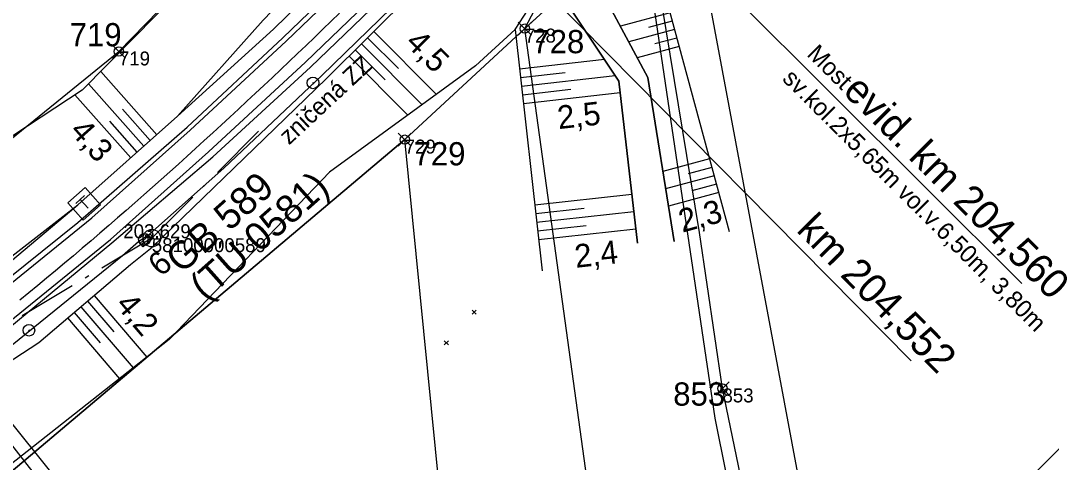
# Model space of a CAD drawing. Extents: x -800194 to -799078, y -1007177 to -1006597.
# Drawn here: x -799466.4 to -799377.8, y -1006944.2 to -1006906.1 of the extents above; entities that cross this region are included whole.
import ezdxf

# ---------------------------------------------------------------- set-up
doc = ezdxf.new("R2010")
doc.units = 0
for name, color, linetype in [('02_Osa_koleje', 7, 'Continuous'), ('Dočasné zábory', 7, 'Continuous'), ('Obvod stavby', 7, 'Continuous'), ('Vrstva 11', 7, 'Continuous'), ('Vrstva 12', 7, 'Continuous'), ('Vrstva 18', 7, 'Continuous'), ('Vrstva 3', 7, 'Continuous'), ('Vrstva 33', 7, 'Continuous'), ('Vrstva 4', 7, 'Continuous'), ('Vrstva 48', 7, 'Continuous'), ('Vrstva 49', 7, 'Continuous'), ('Vrstva 5', 7, 'Continuous'), ('Vrstva 50', 7, 'Continuous'), ('Vrstva 53', 7, 'Continuous'), ('Vrstva 55', 7, 'Continuous'), ('Vrstva 56', 7, 'Continuous'), ('Vrstva 60', 7, 'Continuous'), ('Vrstva 61', 7, 'Continuous'), ('Vrstva 63', 7, 'Continuous'), ('Vrstva 7', 7, 'Continuous')]:
    doc.layers.add(name, color=color, linetype=linetype)

msp = doc.modelspace()

# ---------------------------------------------------------------- linework, layer by layer
at = {"layer": '02_Osa_koleje'}
msp.add_lwpolyline([(-799439.012, -1006905.497), (-799439.73, -1006906.193), (-799440.449, -1006906.887), (-799441.17, -1006907.581), (-799441.891, -1006908.273), (-799442.614, -1006908.965), (-799443.338, -1006909.655), (-799444.063, -1006910.343), (-799444.789, -1006911.03), (-799445.517, -1006911.716), (-799446.246, -1006912.401), (-799446.976, -1006913.084), (-799447.708, -1006913.766), (-799448.441, -1006914.446), (-799449.175, -1006915.124), (-799449.911, -1006915.802), (-799450.649, -1006916.477), (-799451.388, -1006917.151), (-799452.128, -1006917.823), (-799452.87, -1006918.493), (-799453.614, -1006919.162), (-799454.359, -1006919.828), (-799455.106, -1006920.493), (-799455.855, -1006921.156), (-799456.605, -1006921.818), (-799457.357, -1006922.477), (-799458.111, -1006923.134), (-799458.866, -1006923.789), (-799459.623, -1006924.442), (-799460.382, -1006925.093), (-799461.143, -1006925.742), (-799461.906, -1006926.389), (-799462.671, -1006927.033), (-799463.437, -1006927.675), (-799464.206, -1006928.315), (-799464.976, -1006928.953), (-799465.749, -1006929.588), (-799466.523, -1006930.22)], dxfattribs=at)
at = {"layer": 'Dočasné zábory'}
for p, q in [((-799406.631, -1006938.384), (-799405.5, -1006937.253)), ((-799406.631, -1006937.253), (-799405.5, -1006938.384))]:
    msp.add_line(p, q, dxfattribs=at)
for points in [[(-799409.787, -1006894.075), (-799409.48, -1006895.36), (-799407.32, -1006903.81), (-799399.52, -1006945.6), (-799393.3, -1006959.22), (-799387.62, -1006968.78), (-799386.5, -1006977.04), (-799373.965, -1006992.548), (-799373.809, -1006993.118), (-799373.66, -1006993.663), (-799374.581, -1006994.49), (-799377.093, -1006995.576), (-799395.454, -1007003.287), (-799408.652, -1007008.83)], [(-799551.8, -1007065.451), (-799550.158, -1007064.738), (-799440.86, -1007028.935), (-799429.23, -1007018.29), (-799423.8, -1007012.71), (-799421.502, -1007009.702), (-799412.394, -1007002.777), (-799410.562, -1007001.808), (-799396.882, -1006994.578), (-799395.924, -1006994.071), (-799394.941, -1006993.029), (-799394.947, -1006991.657), (-799395.98, -1006986.652), (-799406.066, -1006937.818), (-799408.053, -1006924.38), (-799411.989, -1006900.28), (-799413.453, -1006897.919)]]:
    msp.add_lwpolyline(points, dxfattribs=at)
msp.add_circle((-799406.066, -1006937.818), 0.4, dxfattribs=at)
at = {"layer": 'Obvod stavby'}
for p, q in [((-799423.636, -1006907.396), (-799422.504, -1006906.264)), ((-799423.636, -1006906.264), (-799422.504, -1006907.396)), ((-799458.556, -1006909.366), (-799457.424, -1006908.234)), ((-799458.556, -1006908.234), (-799457.424, -1006909.366)), ((-799433.966, -1006916.956), (-799432.834, -1006915.824)), ((-799433.966, -1006915.824), (-799432.834, -1006916.956))]:
    msp.add_line(p, q, dxfattribs=at)
msp.add_lwpolyline([(-799559.64, -1006968.48), (-799519.68, -1006952.01), (-799500.87, -1006940.41), (-799496.64, -1006937.8), (-799494.85, -1006936.7), (-799484.52, -1006930.32), (-799457.99, -1006908.8), (-799435, -1006885.17), (-799430.26, -1006880.27), (-799425.53, -1006875.38), (-799422.55, -1006864.36), (-799416.748, -1006858.798), (-799395.763, -1006879.374), (-799413.75, -1006898.23), (-799418.41, -1006902.53), (-799423.07, -1006906.83), (-799433.4, -1006916.39), (-799469.5, -1006946.86), (-799487.22, -1006958.47), (-799495.25, -1006963.74), (-799521.98, -1006977.8), (-799546.71, -1006987.83)], dxfattribs=at)
for centre in [(-799423.07, -1006906.83), (-799457.99, -1006908.8), (-799433.4, -1006916.39)]:
    msp.add_circle(centre, 0.4, dxfattribs=at)
at = {"layer": 'Vrstva 11'}
for p, q in [((-799455.418, -1006924.635), (-799456.17, -1006925.303)), ((-799455.51, -1006925.383), (-799455.47, -1006924.681)), ((-799455.891, -1006925.459), (-799455.866, -1006925.033))]:
    msp.add_line(p, q, dxfattribs=at)
msp.add_circle((-799455.794, -1006924.969), 0.503, dxfattribs=at)
msp.add_arc((-799455.794, -1006924.969), 0.503, 221.618, 41.618, dxfattribs=at)
at = {"layer": 'Vrstva 12'}
msp.add_lwpolyline([(-799455.328, -1006924.513), (-799455.013, -1006924.859), (-799455.894, -1006925.627), (-799456.318, -1006925.174), (-799455.328, -1006924.513)], dxfattribs=at)
at = {"layer": 'Vrstva 18'}
msp.add_line((-799380.318, -1006928.766), (-799419.546, -1006889.62), dxfattribs=at)
at = {"layer": 'Vrstva 3'}
msp.add_line((-799442.19, -1006974.528), (-799473.063, -1006935.201), dxfattribs=at)
msp.add_lwpolyline([(-799439.356, -1006972.379), (-799450.062, -1006959.03), (-799451.608, -1006960.27), (-799472.235, -1006934.552)], dxfattribs=at)
at = {"layer": 'Vrstva 33'}
for p, q in [((-799461.686, -1006921.876), (-799460.938, -1006921.212)), ((-799461.312, -1006921.544), (-799460.648, -1006922.292))]:
    msp.add_line(p, q, dxfattribs=at)
msp.add_lwpolyline([(-799462.392, -1006921.835), (-799460.897, -1006920.506), (-799459.568, -1006922.001), (-799461.063, -1006923.33), (-799462.392, -1006921.835)], dxfattribs=at)
at = {"layer": 'Vrstva 4'}
for points in [[(-799510.394, -1006958.536), (-799498.027, -1006951.328), (-799477.988, -1006937.435), (-799460.33, -1006923.117), (-799451.862, -1006915.581), (-799443.604, -1006907.9), (-799435.444, -1006900.067), (-799428.64, -1006893.299), (-799422.817, -1006887.511), (-799415.998, -1006880.595), (-799408.158, -1006872.652), (-799401.02, -1006864.85)], [(-799509.248, -1006960.724), (-799497.456, -1006953.809), (-799476.495, -1006939.437), (-799458.707, -1006924.982), (-799450.277, -1006917.43), (-799441.932, -1006909.717), (-799433.783, -1006901.867), (-799426.9, -1006895.092), (-799421.037, -1006889.182), (-799414.218, -1006882.281), (-799406.443, -1006874.417), (-799398.609, -1006866.93)], [(-799511.236, -1006957.129), (-799499.236, -1006950.771), (-799498.598, -1006949.914), (-799498.679, -1006949.705), (-799496.151, -1006948.479), (-799496.251, -1006948.258), (-799490.687, -1006944.683), (-799490.497, -1006944.878), (-799488.249, -1006943.052), (-799488.105, -1006943.216), (-799486.269, -1006941.68), (-799478.997, -1006936.484), (-799474.568, -1006932.916), (-799474.237, -1006932.694), (-799461.519, -1006921.99), (-799452.935, -1006914.372), (-799444.695, -1006906.886), (-799436.579, -1006898.932), (-799429.629, -1006892.192), (-799429.07, -1006892.727), (-799423.479, -1006886.901), (-799416.56, -1006880.007), (-799417.085, -1006879.46), (-799415.349, -1006878.386)], [(-799510.726, -1006958.045), (-799497.901, -1006950.516), (-799478.36, -1006937.055), (-799461.534, -1006923.53), (-799452.128, -1006915.305), (-799443.894, -1006907.632), (-799435.739, -1006899.754), (-799428.922, -1006893.007), (-799423.223, -1006887.256), (-799416.277, -1006880.269), (-799414.896, -1006878.87)], [(-799509.087, -1006961.127), (-799497.277, -1006954.118), (-799476.183, -1006939.802), (-799458.586, -1006925.284), (-799449.914, -1006917.869), (-799441.499, -1006910.139), (-799433.371, -1006902.28), (-799426.451, -1006895.478), (-799420.657, -1006889.585), (-799413.85, -1006882.742), (-799412.388, -1006881.287)], [(-799475.489, -1006940.774), (-799457.684, -1006926.366), (-799456.318, -1006925.174), (-799455.328, -1006924.513), (-799448.961, -1006918.843), (-799440.534, -1006910.864), (-799432.566, -1006903.097), (-799428.918, -1006899.95), (-799428.131, -1006899.117), (-799425.824, -1006895.981), (-799426.173, -1006895.627), (-799420.283, -1006889.914), (-799413.647, -1006882.957), (-799413.271, -1006883.261), (-799411.693, -1006881.939)]]:
    msp.add_lwpolyline(points, dxfattribs=at)
at = {"layer": 'Vrstva 48'}
for p, q in [((-799410.574, -1006905.468), (-799414.85, -1006906.623)), ((-799410.183, -1006906.916), (-799414.124, -1006907.981)), ((-799410.379, -1006906.192), (-799412.433, -1006906.747)), ((-799436.601, -1006907.611), (-799433.948, -1006910.272)), ((-799436.07, -1006907.081), (-799430.681, -1006912.486)), ((-799409.987, -1006907.64), (-799411.874, -1006908.15)), ((-799437.663, -1006908.67), (-799435.092, -1006911.248)), ((-799437.132, -1006908.141), (-799431.908, -1006913.38)), ((-799409.792, -1006908.364), (-799413.398, -1006909.338)), ((-799438.194, -1006909.2), (-799433.135, -1006914.274)), ((-799423.526, -1006910.286), (-799416.226, -1006909.471)), ((-799454.726, -1006915.962), (-799459.558, -1006910.517)), ((-799423.443, -1006911.031), (-799419.601, -1006910.602)), ((-799423.36, -1006911.777), (-799415.291, -1006910.876)), ((-799455.848, -1006916.957), (-799460.612, -1006911.589)), ((-799423.277, -1006912.522), (-799419.11, -1006912.057)), ((-799456.97, -1006917.953), (-799461.771, -1006912.543)), ((-799423.193, -1006913.268), (-799414.858, -1006912.337)), ((-799455.287, -1006916.459), (-799457.686, -1006913.756)), ((-799456.409, -1006917.455), (-799458.774, -1006914.79)), ((-799407.172, -1006918.053), (-799411.191, -1006919.139)), ((-799406.976, -1006918.777), (-799409.024, -1006919.33)), ((-799406.781, -1006919.501), (-799410.952, -1006920.628)), ((-799406.585, -1006920.225), (-799408.709, -1006920.799)), ((-799422.218, -1006922.007), (-799413.866, -1006921.075)), ((-799406.389, -1006920.949), (-799410.713, -1006922.118)), ((-799422.135, -1006922.753), (-799417.958, -1006922.286)), ((-799422.051, -1006923.498), (-799413.697, -1006922.565)), ((-799421.968, -1006924.243), (-799417.79, -1006923.777)), ((-799421.885, -1006924.989), (-799413.528, -1006924.056)), ((-799460.115, -1006929.802), (-799455.59, -1006935.113)), ((-799461.257, -1006930.774), (-799456.769, -1006936.043)), ((-799460.686, -1006930.288), (-799458.433, -1006932.933)), ((-799462.399, -1006931.747), (-799457.948, -1006936.972)), ((-799461.828, -1006931.261), (-799459.593, -1006933.884))]:
    msp.add_line(p, q, dxfattribs=at)
at = {"layer": 'Vrstva 49'}
for p, q in [((-799423.903, -1006906.911), (-799421.584, -1006927.684)), ((-799427.607, -1006931.077), (-799427.253, -1006931.431)), ((-799427.607, -1006931.431), (-799427.253, -1006931.077)), ((-799429.993, -1006933.713), (-799429.639, -1006934.067)), ((-799429.993, -1006934.067), (-799429.639, -1006933.713))]:
    msp.add_line(p, q, dxfattribs=at)
for points in [[(-799410.227, -1006925.149), (-799412.491, -1006911.033), (-799419.106, -1006898.668), (-799423.582, -1006889.778), (-799429.735, -1006878.378), (-799431.818, -1006855.328)], [(-799426.038, -1006858.234), (-799426.419, -1006863.568), (-799427.212, -1006869.673), (-799426.968, -1006870.003), (-799426.4, -1006870.552), (-799426.115, -1006870.824), (-799426.018, -1006877.519), (-799424.103, -1006883.903), (-799422.705, -1006885.358), (-799423.751, -1006886.402), (-799420.096, -1006889.979), (-799419.086, -1006888.964), (-799412.022, -1006900.113), (-799405.487, -1006924.286)], [(-799429.125, -1006891.656), (-799433.133, -1006889.484), (-799437.572, -1006888.963), (-799439.693, -1006890.332), (-799461.15, -1006912.135), (-799487.142, -1006929.222), (-799487.006, -1006931.546), (-799490.308, -1006935.771)], [(-799490.09, -1006944.145), (-799488.194, -1006942.597), (-799488.011, -1006942.815), (-799488.011, -1006942.815), (-799486.419, -1006941.508), (-799486.269, -1006941.68), (-799484.618, -1006939.109), (-799474.926, -1006932.405), (-799474.596, -1006932.171), (-799461.519, -1006921.99), (-799452.935, -1006914.372), (-799445.566, -1006906.106), (-799432.588, -1006892.596), (-799429.125, -1006891.656)], [(-799486.865, -1006949.018), (-799484.86, -1006947.727), (-799485.016, -1006947.459), (-799485.713, -1006947.881), (-799483.734, -1006946.536), (-799483.686, -1006946.569), (-799483.396, -1006947.063), (-799482.389, -1006946.51), (-799482.647, -1006946.068), (-799475.489, -1006940.774), (-799464.892, -1006933.871), (-799456.989, -1006927.138), (-799455.117, -1006925.642), (-799440.165, -1006911.165), (-799428.918, -1006899.95), (-799428.299, -1006900.544), (-799427.466, -1006899.73), (-799428.131, -1006899.117), (-799426.509, -1006898.237), (-799425.17, -1006895.342)], [(-799413.387, -1006925.296), (-799414.969, -1006911.36), (-799421.688, -1006901.262)], [(-799423.903, -1006906.911), (-799421.655, -1006903.434)], [(-799423.903, -1006906.911), (-799427.313, -1006910.033), (-799439.866, -1006919.177), (-799453.667, -1006933.596), (-799478.523, -1006953.199), (-799482.72, -1006952.931), (-799486.865, -1006949.018)]]:
    msp.add_lwpolyline(points, dxfattribs=at)
at = {"layer": 'Vrstva 5'}
msp.add_line((-799389.844, -1006935.446), (-799426.915, -1006897.844), dxfattribs=at)
at = {"layer": 'Vrstva 50'}
msp.add_line((-799441.33, -1006911.537), (-799441.256, -1006911.469), dxfattribs=at)
for points in [[(-799431.818, -1006855.328), (-799429.735, -1006878.378), (-799423.582, -1006889.778), (-799419.106, -1006898.668), (-799412.491, -1006911.033), (-799410.227, -1006925.149)], [(-799433.824, -1006862.471), (-799432.369, -1006880.085), (-799427.694, -1006890.471), (-799424.101, -1006893.992), (-799424.223, -1006894.144), (-799421.688, -1006901.262), (-799414.969, -1006911.36), (-799413.387, -1006925.296)]]:
    msp.add_lwpolyline(points, dxfattribs=at)
msp.add_circle((-799441.293, -1006911.503), 0.5, dxfattribs=at)
at = {"layer": 'Vrstva 53'}
for points in [[(-799559.64, -1006968.48), (-799519.68, -1006952.01), (-799500.87, -1006940.41), (-799496.64, -1006937.8), (-799494.85, -1006936.7), (-799484.519, -1006930.319), (-799457.99, -1006908.8), (-799435, -1006885.17), (-799430.26, -1006880.27), (-799425.53, -1006875.38), (-799422.55, -1006864.36), (-799390.88, -1006834), (-799358.35, -1006806.65), (-799352.29, -1006801.56), (-799330.91, -1006783.58), (-799314.235, -1006766.649)], [(-799312.398, -1006791.976), (-799331.37, -1006811.87), (-799413.75, -1006898.23), (-799418.41, -1006902.53), (-799423.07, -1006906.83), (-799433.4, -1006916.39), (-799469.5, -1006946.86), (-799487.22, -1006958.47), (-799495.25, -1006963.74), (-799521.98, -1006977.8), (-799546.71, -1006987.83)]]:
    msp.add_lwpolyline(points, dxfattribs=at)
at = {"layer": 'Vrstva 55'}
for p, q in [((-799423.07, -1006906.83), (-799418.41, -1006902.53)), ((-799433.4, -1006916.39), (-799423.07, -1006906.83)), ((-799424.1, -1007009.73), (-799433.4, -1006916.39)), ((-799393.3, -1006959.22), (-799364.81, -1006930.69))]:
    msp.add_line(p, q, dxfattribs=at)
for points in [[(-799494.85, -1006936.7), (-799484.52, -1006930.32), (-799457.99, -1006908.8), (-799435, -1006885.17)], [(-799413.75, -1006898.23), (-799411.99, -1006904.75), (-799406.72, -1006940.36), (-799397.01, -1006988.73)], [(-799407.32, -1006903.81), (-799399.52, -1006945.6), (-799393.3, -1006959.22)], [(-799410.89, -1007000.14), (-799412.5, -1006983.38), (-799423.07, -1006906.83)], [(-799487.22, -1006958.47), (-799469.5, -1006946.86), (-799433.4, -1006916.39)]]:
    msp.add_lwpolyline(points, dxfattribs=at)
at = {"layer": 'Vrstva 56'}
msp.add_line((-799423.07, -1006906.83), (-799421, -1006902.84), dxfattribs=at)
at = {"layer": 'Vrstva 60'}
for p, q in [((-799423.07, -1006906.83), (-799423.07, -1006906.83)), ((-799457.99, -1006908.8), (-799457.99, -1006908.8)), ((-799433.4, -1006916.39), (-799433.4, -1006916.39)), ((-799455.158, -1006924.878), (-799455.158, -1006924.878)), ((-799406.066, -1006937.818), (-799406.066, -1006937.818))]:
    msp.add_line(p, q, dxfattribs=at)
at = {"layer": 'Vrstva 63'}
for p, q in [((-799449.511, -1006919.212), (-799445.981, -1006915.67)), ((-799450.711, -1006920.416), (-799450.428, -1006920.132)), ((-799455.158, -1006924.878), (-799451.628, -1006921.336)), ((-799455.158, -1006924.878), (-799459.448, -1006927.447)), ((-799455.195, -1006924.911), (-799455.121, -1006924.845)), ((-799460.563, -1006928.115), (-799460.906, -1006928.321)), ((-799462.021, -1006928.988), (-799466.311, -1006931.558))]:
    msp.add_line(p, q, dxfattribs=at)
msp.add_circle((-799455.158, -1006924.878), 0.756, dxfattribs=at)
at = {"layer": 'Vrstva 7'}
msp.add_line((-799465.764, -1006932.836), (-799465.688, -1006932.772), dxfattribs=at)
msp.add_circle((-799465.726, -1006932.804), 0.5, dxfattribs=at)

# ---------------------------------------------------------------- texts
at = {"layer": 'Dočasné zábory'}
msp.add_text('853', height=2, rotation=360, dxfattribs=at).set_placement((-799410.299, -1006939.295))
at = {"layer": 'Obvod stavby'}
for s, p in [('719', (-799462.22, -1006908.352)), ('728', (-799422.418, -1006908.949)), ('729', (-799432.638, -1006918.605))]:
    msp.add_text(s, height=2, rotation=360, dxfattribs=at).set_placement(p)
at = {"layer": 'Vrstva 11'}
msp.add_text('6', height=2, rotation=41.618, dxfattribs=at).set_placement((-799454.367, -1006928.264))
at = {"layer": 'Vrstva 18'}
for s, height, p in [('Most', 1.5, (-799398.873, -1006909.11)), ('sv.kol.2x5,65m vol.v.6,50m, 3,80m', 1.5, (-799400.992, -1006911.233)), ('evid. km 204,560', 2.5, (-799395.797, -1006912.325))]:
    msp.add_text(s, height=height, rotation=315.05951, dxfattribs=at).set_placement(p)
at = {"layer": 'Vrstva 48'}
for s, rotation, p in [('4,5', 314.91837, (-799433.431, -1006908.143)), ('2,5', 6.36986, (-799420.157, -1006915.489)), ('4,3', 311.58793, (-799462.304, -1006915.704)), ('2,3', 15.12789, (-799409.526, -1006924.407)), ('2,4', 6.36986, (-799418.675, -1006927.434)), ('4,2', 310.4295, (-799458.357, -1006930.642))]:
    msp.add_text(s, height=2, rotation=rotation, dxfattribs=at).set_placement(p)
at = {"layer": 'Vrstva 5'}
msp.add_text('km 204,552', height=2.5, rotation=314.59271, dxfattribs=at).set_placement((-799399.785, -1006924.248))
at = {"layer": 'Vrstva 50'}
msp.add_text('zničená ZZ', height=1.5, rotation=42.88445, dxfattribs=at).set_placement((-799443.358, -1006916.901))
at = {"layer": 'Vrstva 60'}
for s, p in [('728', (-799423.07, -1006908.03)), ('719', (-799457.99, -1006910)), ('729', (-799433.4, -1006917.59)), ('58100000589', (-799455.158, -1006926.078)), ('853', (-799406.066, -1006939.018))]:
    msp.add_text(s, height=1.2, dxfattribs=at).set_placement(p)
at = {"layer": 'Vrstva 61'}
msp.add_text('203.629', height=1.2, dxfattribs=at).set_placement((-799457.612, -1006924.878))
at = {"layer": 'Vrstva 63'}
for s, p in [('GB 589', (-799452.612, -1006928.004)), ('(TÚ 0581)', (-799450.549, -1006930.326))]:
    msp.add_text(s, height=2.4, rotation=41.618, dxfattribs=at).set_placement(p)

doc.saveas('drawing.dxf')
